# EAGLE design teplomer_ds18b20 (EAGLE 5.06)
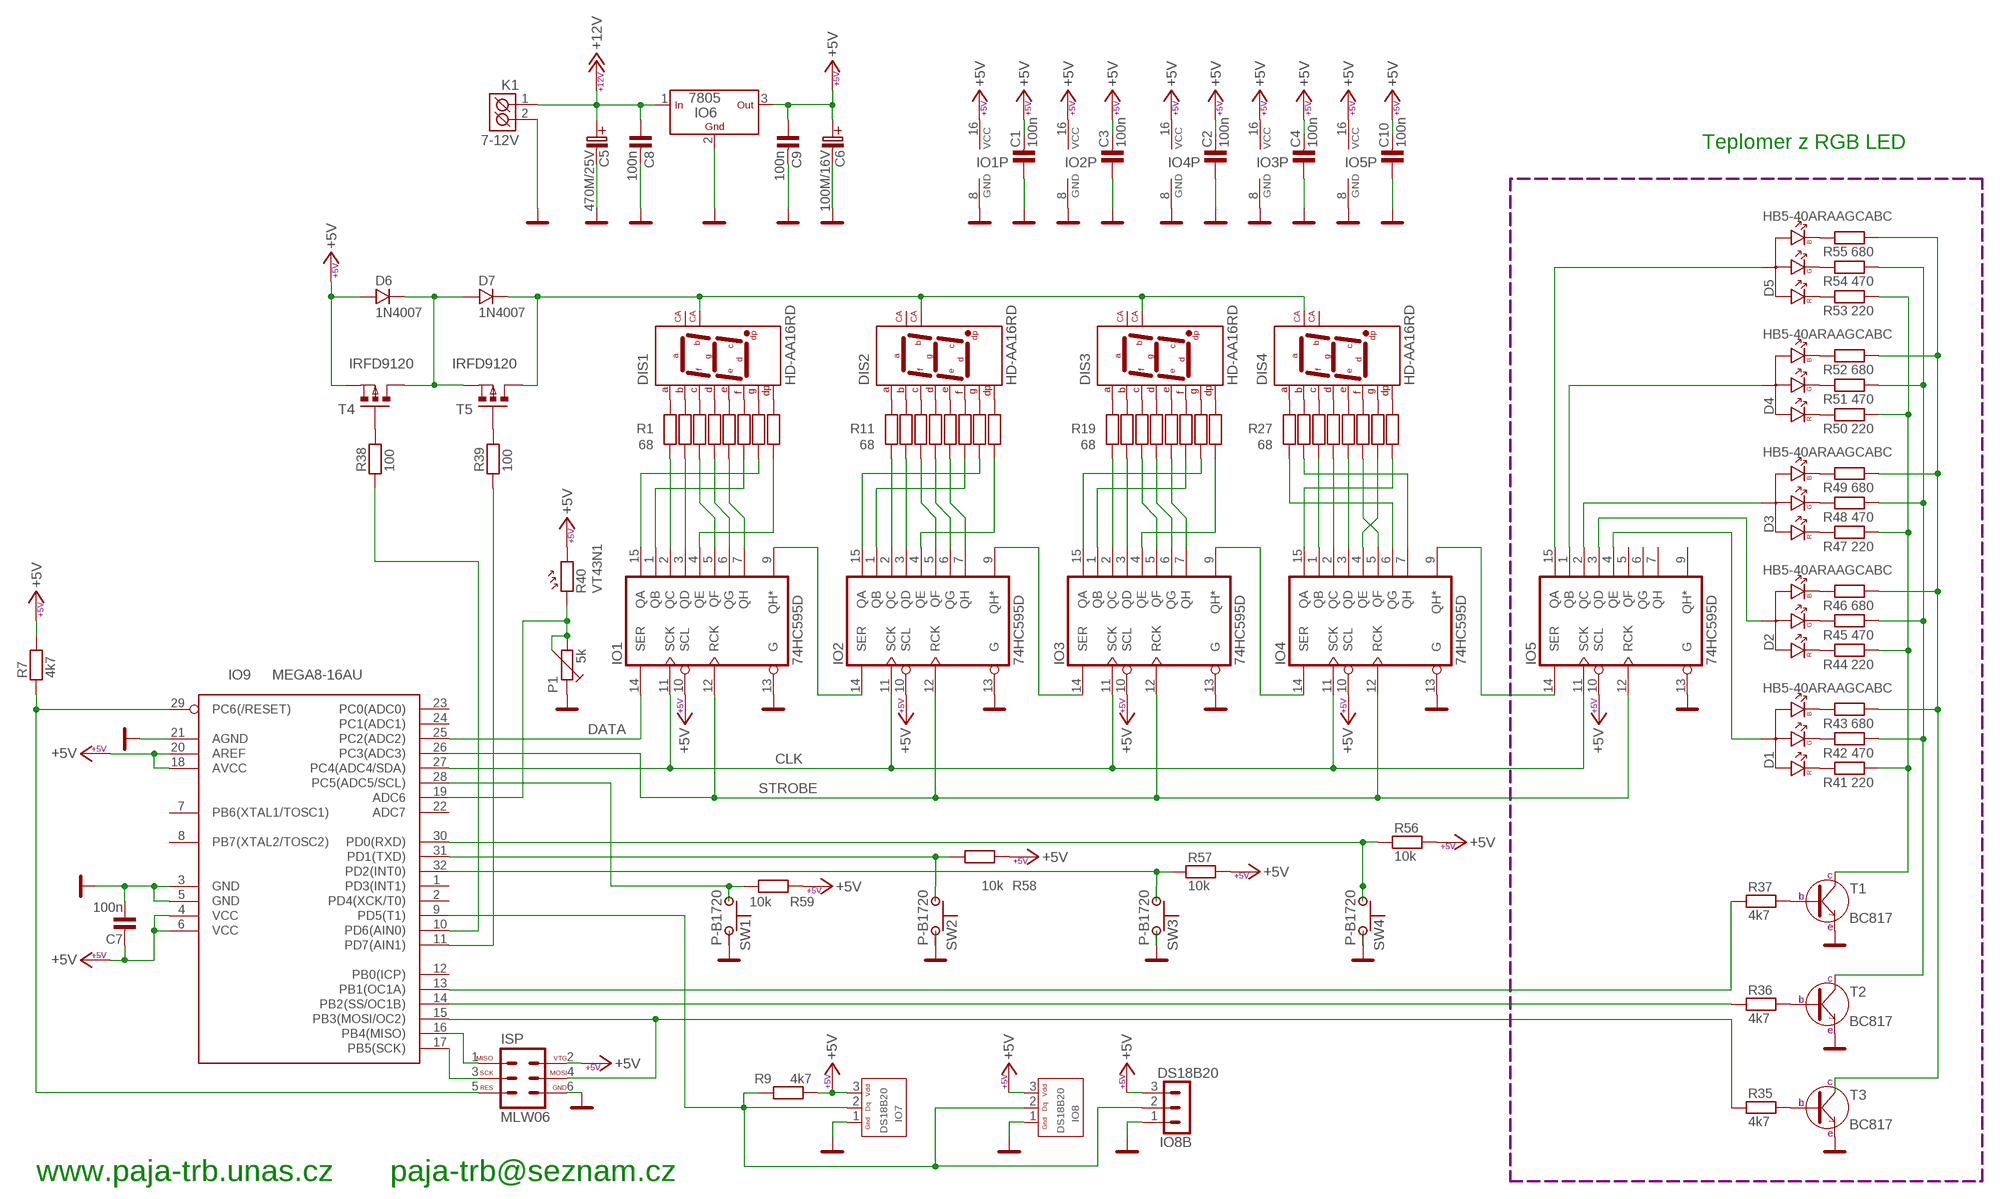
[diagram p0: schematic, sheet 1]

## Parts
C1  100n  C-KERAMIK_SMD_1206  [1206]
C2  100n  C-KERAMIK_SMD_1206  [1206]
C3  100n  C-KERAMIK_SMD_1206  [1206]
C4  100n  C-KERAMIK_SMD_1206  [1206]
C5  470M/25V  [C_EL_5]
C6  100M/16V  [C_EL_2,5]
C7  100n  C-KERAMIK_SMD_1206  [1206]
C8  100n  C-KERAMIK_SMD_1206  [1206]
C9  100n  C-KERAMIK_SMD_1206  [1206]
C10  100n  C-KERAMIK_SMD_1206  [1206]
D1  HB5-40ARAAGCABC  LED_RGB  [LED_5-RGB]
D2  HB5-40ARAAGCABC  LED_RGB  [LED_5-RGB]
D3  HB5-40ARAAGCABC  LED_RGB  [LED_5-RGB]
D4  HB5-40ARAAGCABC  LED_RGB  [LED_5-RGB]
D5  HB5-40ARAAGCABC  LED_RGB  [LED_5-RGB]
D6  1N4007  1N4007_SM-1  [SM-1]
D7  1N4007  1N4007_SM-1  [SM-1]
DIS1  HD-AA16RD  HD-AA11RD  [HD-AA]
DIS2  HD-AA16RD  HD-AA11RD  [HD-AA]
DIS3  HD-AA16RD  HD-AA11RD  [HD-AA]
DIS4  HD-AA16RD  HD-AA11RD  [HD-AA]
IO1  74HC595D  [SO16]
IO2  74HC595D  [SO16]
IO3  74HC595D  [SO16]
IO4  74HC595D  [SO16]
IO5  74HC595D  [SO16]
IO6  7805  78_LEZ_LEZ  [TO-220]
IO7  DS18B20  DS18B20TO-92  [TO-92]
IO8  DS18B20  DS18B20TO-92  [TO-92]
IO8B  DS18B20  PSH02-03W  [PSH02-03W]
IO9  MEGA8-16AU  MEGA8-AI  [TQFP32-08]
ISP  MLW06  AVR_ISP  [MLW06G]
K1  7-12V  ARK500/2  [ARK500/2]
P1  5k  TRIMRPT6V  [PT6V]
R1  68  R_SMD_1206  [1206]
R2  68  R_SMD_1206  [1206]
R3  68  R_SMD_1206  [1206]
R4  68  R_SMD_1206  [1206]
R5  68  R_SMD_1206  [1206]
R6  68  R_SMD_1206  [1206]
R7  4k7  R_SMD_1206  [1206]
R8  68  R_SMD_1206  [1206]
R9  4k7  R_SMD_1206  [1206]
R10  470  R_SMD_1206  [1206]
R11  68  R_SMD_1206  [1206]
R12  68  R_SMD_1206  [1206]
R13  68  R_SMD_1206  [1206]
R14  68  R_SMD_1206  [1206]
R15  68  R_SMD_1206  [1206]
R16  68  R_SMD_1206  [1206]
R17  68  R_SMD_1206  [1206]
R18  470  R_SMD_1206  [1206]
R19  68  R_SMD_1206  [1206]
R20  68  R_SMD_1206  [1206]
R21  68  R_SMD_1206  [1206]
R22  68  R_SMD_1206  [1206]
R23  68  R_SMD_1206  [1206]
R24  68  R_SMD_1206  [1206]
R25  68  R_SMD_1206  [1206]
R26  470  R_SMD_1206  [1206]
R27  68  R_SMD_1206  [1206]
R28  68  R_SMD_1206  [1206]
R29  68  R_SMD_1206  [1206]
R30  68  R_SMD_1206  [1206]
R31  68  R_SMD_1206  [1206]
R32  68  R_SMD_1206  [1206]
R33  470  R_SMD_1206  [1206]
R34  68  R_SMD_1206  [1206]
R35  4k7  R_SMD_1206  [1206]
R36  4k7  R_SMD_1206  [1206]
R37  4k7  R_SMD_1206  [1206]
R38  100  R_7,5  [R-7,5]
R39  100  R_7,5  [R-7,5]
R40  VT43N1  R-FOTO  [R-FOTO]
R41  220  R_SMD_0805  [0805]
R42  470  R_SMD_1206  [1206]
R43  680  R_SMD_1206  [1206]
R44  220  R_SMD_0805  [0805]
R45  470  R_SMD_1206  [1206]
R46  680  R_SMD_1206  [1206]
R47  220  R_SMD_0805  [0805]
R48  470  R_SMD_1206  [1206]
R49  680  R_SMD_1206  [1206]
R50  220  R_SMD_0805  [0805]
R51  470  R_SMD_1206  [1206]
R52  680  R_SMD_1206  [1206]
R53  220  R_SMD_0805  [0805]
R54  470  R_SMD_1206  [1206]
R55  680  R_SMD_1206  [1206]
R56  10k  R_10  [R-10]
R57  10k  R_7,5  [R-7,5]
R58  10k  R_SMD_1206  [1206]
R59  10k  R_10  [R-10]
SW1  P-B1720  [P-B1720]
SW2  P-B1720  [P-B1720]
SW3  P-B1720  [P-B1720]
SW4  P-B1720  [P-B1720]
T1  BC817  [SOT-23]
T2  BC817  [SOT-23]
T3  BC817  [SOT-23]
T4  IRFD9120  IRFD9120*  [DIL04]
T5  IRFD9120  IRFD9120*  [DIL04]

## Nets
0,7: IO9.10(PD6(AIN0)) R38.1
1,4: IO9.11(PD7(AIN1)) R39.1
1WIRE: IO7.2(1WIRE) IO8.2(1WIRE) IO8B.2 IO9.9(PD5(T1)) R9.1
+5V: C1.2 C2.2 C3.2 C4.2 C6.C+(C_EL+) C7.2 C9.1 C10.2 D6.A IO1.10(SCL) IO1.16(VCC) IO2.10(SCL) IO2.16(VCC) IO3.10(SCL) IO3.16(VCC) IO4.10(SCL) IO4.16(VCC) IO5.10(SCL) IO5.16(VCC) IO6.3(OUT) IO7.3(+VCC) IO8.3(+VCC) IO8B.3 IO9.4(VCC) IO9.6(VCC) IO9.18(AVCC) IO9.20(AREF) ISP.2 R7.2 R9.2 R40.2 R56.2 R57.2 R58.2 R59.2 T4.2(S)
+12V: C5.C+(C_EL+) C8.1 IO6.1(IN) K1.1(K1)
B: IO9.14(PB2(SS/OC1B)) R36.1
CLK: IO1.11(SCK) IO2.11(SCK) IO3.11(SCK) IO4.11(SCK) IO5.11(SCK) IO9.27(PC4(ADC4/SDA))
DATA: IO1.14(SER) IO9.25(PC2(ADC2))
G: IO9.15(PB3(MOSI/OC2)) ISP.4 R35.1
GND: C1.1 C2.1 C3.1 C4.1 C5.C-(C_EL-) C6.C-(C_EL-) C7.1 C8.2 C9.2 C10.1 IO1.8(GND) IO1.13(G) IO2.8(GND) IO2.13(G) IO3.8(GND) IO3.13(G) IO4.8(GND) IO4.13(G) IO5.8(GND) IO5.13(G) IO6.2(GND) IO7.1(GND) IO8.1(GND) IO8B.1 IO9.3(GND) IO9.5(GND) IO9.21(AGND) ISP.6 K1.2(K2) P1.1 SW1.2 SW1.4 SW2.2 SW2.4 SW3.2 SW3.4 SW4.2 SW4.4 T1.2(E) T2.2(E) T3.2(E)
MISO: IO9.16(PB4(MISO)) ISP.1
N$1: D6.K D7.A T4.3(D) T5.2(S)
N$2: IO9.19(ADC6) P1.2 P1.3 R40.1
N$3: IO1.9(QH*) IO2.14(SER)
N$4: IO2.9(QH*) IO3.14(SER)
N$5: DIS1.5(DP) R10.2
N$6: IO1.1(QB) R6.1
N$7: IO1.15(QA) R8.1
N$8: IO4.9(QH*) IO5.14(SER)
N$9: IO1.2(QC) R1.1
N$10: IO1.3(QD) R2.1
N$11: IO1.4(QE) R10.1
N$12: IO1.5(QF) R3.1
N$13: D1.2(A) IO5.4(QE)
N$14: DIS1.7(A) R1.2
N$15: DIS1.6(B) R2.2
N$16: DIS1.4(C) R3.2
N$17: DIS1.2(D) R4.2
N$18: DIS1.1(E) R5.2
N$19: DIS1.9(F) R6.2
N$20: DIS1.10(G) R8.2
N$21: IO1.6(QG) R4.1
N$22: IO1.7(QH) R5.1
N$23: IO2.1(QB) R16.1
N$24: IO2.15(QA) R17.1
N$25: IO2.2(QC) R11.1
N$26: IO2.3(QD) R12.1
N$27: IO2.4(QE) R18.1
N$28: IO2.5(QF) R13.1
N$29: IO2.6(QG) R14.1
N$30: IO2.7(QH) R15.1
N$31: DIS2.7(A) R11.2
N$32: DIS2.6(B) R12.2
N$33: DIS2.4(C) R13.2
N$34: DIS2.2(D) R14.2
N$35: DIS2.1(E) R15.2
N$36: DIS2.9(F) R16.2
N$37: DIS2.10(G) R17.2
N$38: DIS2.5(DP) R18.2
N$39: IO3.1(QB) R24.1
N$40: IO3.15(QA) R25.1
N$41: IO3.2(QC) R19.1
N$42: IO3.3(QD) R20.1
N$43: IO3.4(QE) R26.1
N$44: IO3.9(QH*) IO4.14(SER)
N$45: IO3.5(QF) R21.1
N$46: IO3.6(QG) R22.1
N$47: IO3.7(QH) R23.1
N$48: IO4.1(QB) R32.1
N$49: IO4.15(QA) R33.1
N$50: IO4.2(QC) R27.1
N$51: IO4.3(QD) R28.1
N$52: IO4.4(QE) R34.1
N$53: IO4.5(QF) R29.1
N$54: IO4.6(QG) R30.1
N$55: IO4.7(QH) R31.1
N$56: DIS3.7(A) R19.2
N$57: DIS3.6(B) R20.2
N$58: DIS3.4(C) R21.2
N$59: DIS3.2(D) R22.2
N$60: DIS3.1(E) R23.2
N$61: DIS3.9(F) R24.2
N$62: DIS3.10(G) R25.2
N$63: DIS3.5(DP) R26.2
N$64: DIS4.2(D) R27.2
N$65: DIS4.1(E) R28.2
N$66: DIS4.9(F) R29.2
N$67: DIS4.7(A) R30.2
N$68: DIS4.6(B) R31.2
N$69: DIS4.4(C) R32.2
N$70: DIS4.5(DP) R33.2
N$71: DIS4.10(G) R34.2
N$72: IO9.31(PD1(TXD)) R58.1 SW2.1 SW2.3
N$73: R37.2 T1.1(B)
N$74: R36.2 T2.1(B)
N$75: R35.2 T3.1(B)
N$76: R43.1 R46.1 R49.1 R52.1 R55.1 T3.3(C)
N$77: R42.1 R45.1 R48.1 R51.1 R54.1 T2.3(C)
N$78: R41.1 R44.1 R47.1 R50.1 R53.1 T1.3(C)
N$79: D2.2(A) IO5.3(QD)
N$80: D3.2(A) IO5.2(QC)
N$81: D4.2(A) IO5.1(QB)
N$82: D5.2(A) IO5.15(QA)
N$83: IO9.30(PD0(RXD)) R56.1 SW4.1 SW4.3
N$84: IO9.28(PC5(ADC5/SCL)) R59.1 SW1.1 SW1.3
N$85: D1.1(R) R41.2
N$86: R38.2 T4.1(G)
N$87: R39.2 T5.1(G)
N$88: IO9.32(PD2(INT0)) R57.1 SW3.1 SW3.3
N$89: D1.3(G) R42.2
N$90: D1.4(B) R43.2
N$91: D2.1(R) R44.2
N$92: D2.3(G) R45.2
N$93: D2.4(B) R46.2
N$94: D3.1(R) R47.2
N$95: D3.3(G) R48.2
N$96: D3.4(B) R49.2
N$97: D4.1(R) R50.2
N$98: D4.3(G) R51.2
N$99: D4.4(B) R52.2
N$100: D5.1(R) R53.2
N$101: D5.3(G) R54.2
N$102: D5.4(B) R55.2
N$103: D7.K DIS1.8(CA2) DIS2.8(CA2) DIS3.8(CA2) DIS4.3(CA1) T5.3(D)
R: IO9.13(PB1(OC1A)) R37.1
RESET: IO9.29(PC6(/RESET)) ISP.5 R7.1
SCK: IO9.17(PB5(SCK)) ISP.3
STROBE: IO1.12(RCK) IO2.12(RCK) IO3.12(RCK) IO4.12(RCK) IO5.12(RCK) IO9.26(PC3(ADC3))
Unconnected: DIS1.3(CA1) DIS2.3(CA1) DIS3.3(CA1) DIS4.8(CA2) IO5.5(QF) IO5.6(QG) IO5.7(QH) IO5.9(QH*) IO9.1(PD3(INT1)) IO9.2(PD4(XCK/T0)) IO9.7(PB6(XTAL1/TOSC1)) IO9.8(PB7(XTAL2/TOSC2)) IO9.12(PB0(ICP)) IO9.22(ADC7) IO9.23(PC0(ADC0)) IO9.24(PC1(ADC1))

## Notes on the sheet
- Teplomer z RGB LED
- www.paja-trb.unas.cz | paja-trb@seznam.cz

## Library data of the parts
C1-C4 C7-C10 = #PaJa_23_e56:C-KERAMIK: Kondenzator - keramicky
C5 = #PaJa_C-el_2:470M/25V
C6 = #PaJa_C-el_2:100M/16V
D1-D5 = #PaJa_23_e56:LED_RGB: LED dioda - RGB - trojbarevna - 4 vyvody, spol. Anoda
D6 D7 = #PaJa_23_e56:1N4007: Usmernovaci dioda - 1A, 1000V
DIS1-DIS4 = #_GM99:HD-AA11RD
IO1-IO5 = 74xx-eu:74*595: 8-bit SHIFT REGISTER, output latch
IO6 = #PaJa_23_e56:78??: Stabilizátor - 1A a 1,5A ?? - napeti => 05, 06, 08, 09, 12, 15, 18, 20, 24 => 1,5A ?? - napeti => 10, 12, 15, 18 => 1A S ?? - napeti => 05, 09, 10, 12, 15, 18, 24 => 2A T ?? - napeti => 05 => 3A
IO7 IO8 = #PaJa_23_e56:DS18B20: DS18B20 - teplomer, 1wire (-55 az 125°C)
IO8B = #PaJa_23_e56:PSH02-03: Konektory se zamkem - vidlice - 3pin
IO9 = atmel-1:MEGA8: MICROCONTROLLER 8 Kbytes FLASH 1 kbytes SRAM 512 bytes EEPROM USART 6-channel 10 bit ADC 2-channel 8 bit ADC
ISP = #PaJa_23_e56:AVR_ISP
K1 = #PaJa_23_e56:ARK500/2: Svorkovnice - roztec 5mm - dvojita
P1 = #PaJa_23_e56:TRIMR: Trimr
R1-R39 R41-R55 = #PaJa_23_e56:R: Rezistor
R40 = #PaJa_23_e56:R-FOTO: Foto odpor
R56-R59 = #PaJa_23:R: Rezistor
SW1-SW4 = #PaJa_23_e56:P-B1720: &micro;-tlacitko
T1-T3 = #PaJa_23_e56:BC817: SMD tranzistor - NPN - ekv. BC337
T4 T5 = #hacesoft:IRFD9120

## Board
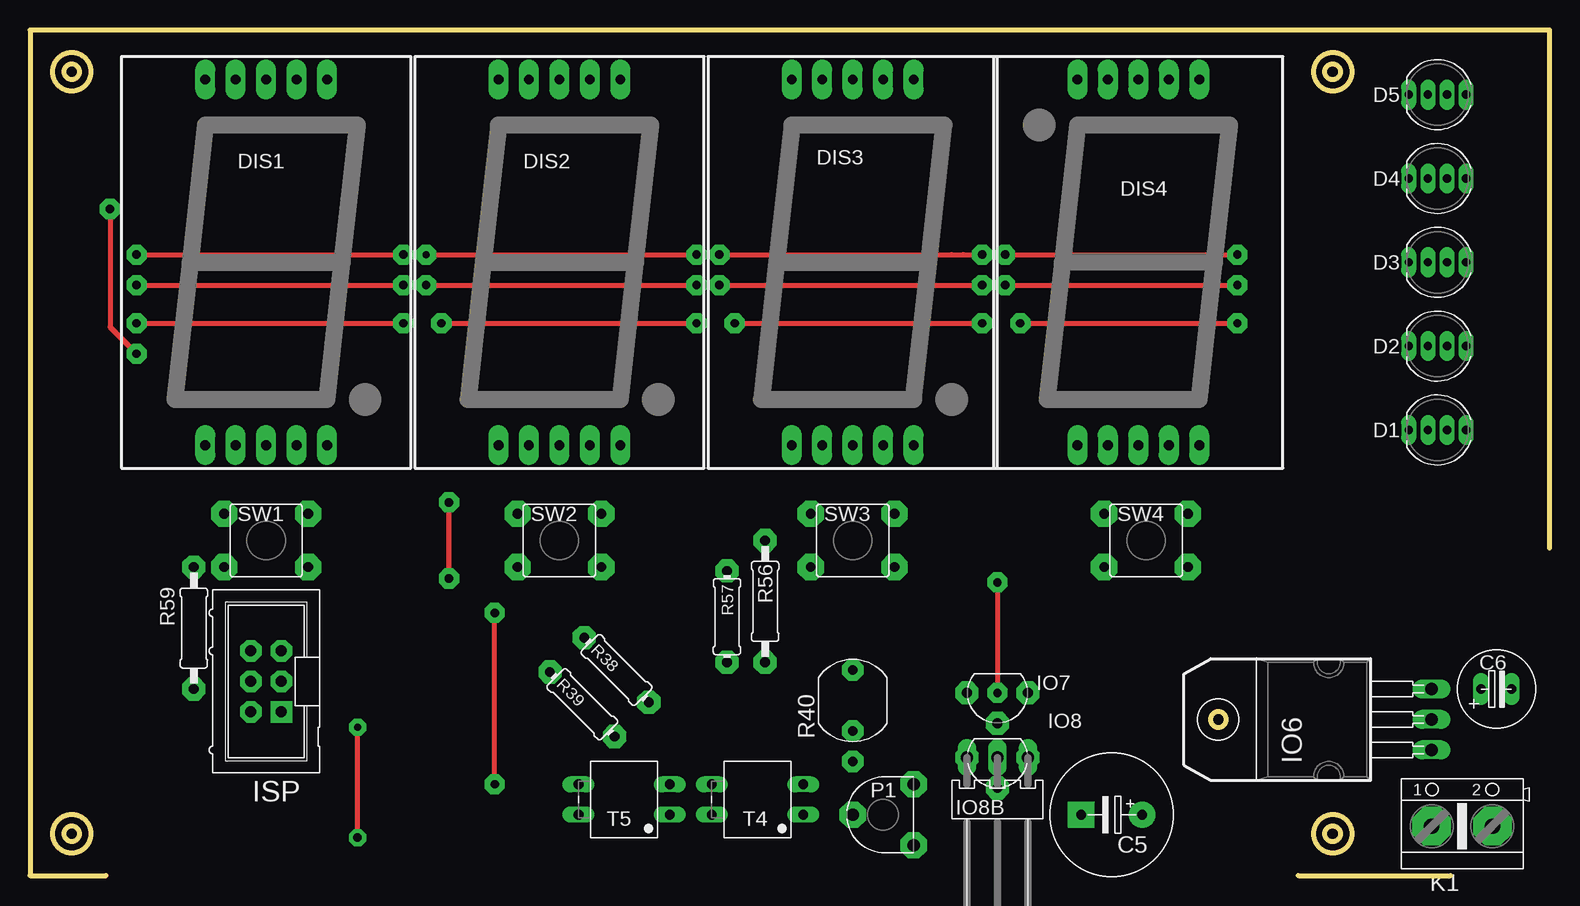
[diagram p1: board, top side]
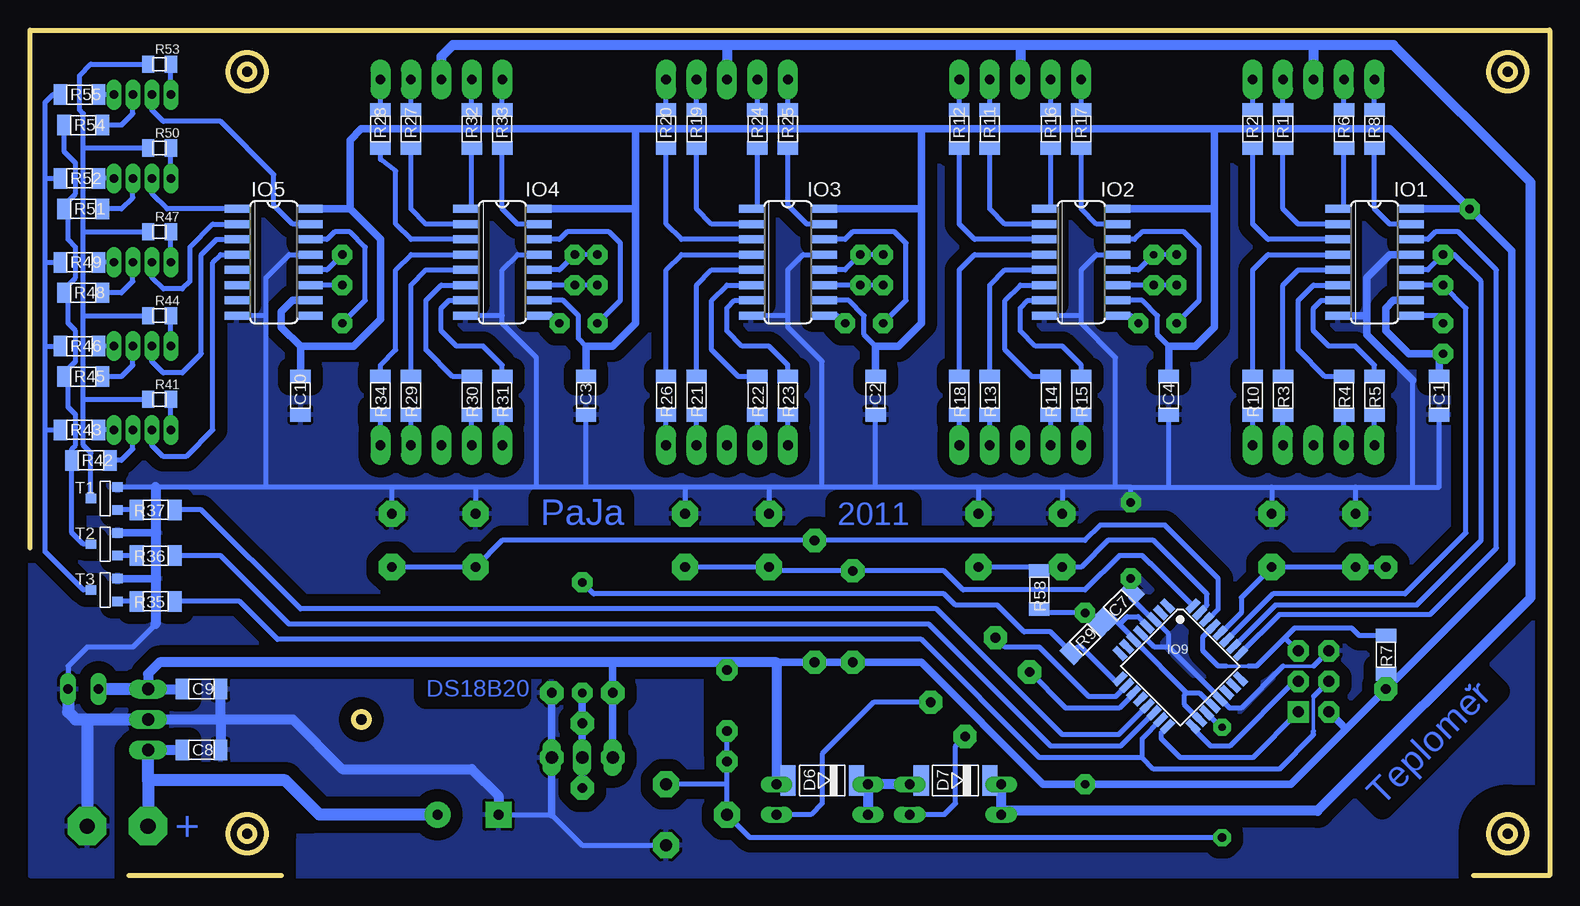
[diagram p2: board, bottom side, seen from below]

Size 126.68 x 70.47 mm. Coordinates in mm from the lower left corner, seen from the top.
Outline: 126.68,27.3 126.67,70.47 0,70.47 0,0 6.35,0
Outline: 105.73,0 118.43,0
Outline: circle at 99.06,13.02 radius 0.64
Outline: circle at 108.58,3.49 radius 1.59
Outline: circle at 3.49,3.49 radius 1.59
Outline: circle at 3.49,3.49 radius 0.64
Outline: circle at 3.49,66.99 radius 0.64
Outline: circle at 3.49,66.99 radius 1.59
Outline: circle at 108.58,66.99 radius 0.64
Outline: circle at 108.58,66.99 radius 1.59
Outline: circle at 108.58,3.49 radius 0.64
Copper layers (1*16): Top 0.035mm / dielectric 1.5mm / Bottom 0.035mm
Design rules "default": minimum track width 10mil, minimum drill 24mil, track to track 8mil, track to pad 8mil, pad to pad 8mil, via to via 8mil, smd to smd 8mil, copper to edge 40mil, drill to drill 8mil, minimum pad ring 10mil, minimum via ring 8mil, stop-mask expansion 4mil, vias tented up to drill 0mil, thermal gap 10mil
Holes 3.2 mm at 3.49,3.49 3.49,66.99 108.58,66.99 108.58,3.49
bRestrict: area 35.9,22.2 to 37.1,24.1; area 0.6,0.6 to 6.3,6.3; area 105.7,0.6 to 111.4,6.3; 6 lines

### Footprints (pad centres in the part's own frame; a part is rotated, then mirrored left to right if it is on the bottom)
1206 = smd 1.143 x 1.702: 1 -1.587,0; 2 1.587,0
C_EL_5 = drill 0.813 pad 2.184 round: C+ -2.54,0 | drill 0.813 pad 2.184 square: C- 2.54,0
C_EL_2,5 = drill 0.813 pad 1.27 long: C+ -1.27,0; C- 1.27,0
LED_5-RGB = drill 0.7 pad 1.27 long: 1 -2.54,0; 2 -0.953,0; 3 0.635,0; 4 2.223,0
SM-1 = smd 1.27 x 2.54: A 2.857,0; K -2.857,0
HD-AA = drill 0.813 pad 1.676 long: 1 0,0; 2 2.54,0; 3 5.08,0; 4 7.62,0; 5 10.16,0; 6 10.16,30.48; 7 7.62,30.48; 8 5.08,30.48; 9 2.54,30.48; 10 0,30.48
SO16 = smd 0.66 x 2.032: 1 -4.445,-3.073; 2 -3.175,-3.073; 3 -1.905,-3.073; 4 -0.635,-3.073; 5 0.635,-3.073; 6 1.905,-3.073; 7 3.175,-3.073; 8 4.445,-3.073; 9 4.445,3.073; 10 3.175,3.073; 11 1.905,3.073; 12 0.635,3.073; 13 -0.635,3.073; 14 -1.905,3.073; 15 -3.175,3.073; 16 -4.445,3.073
TO-220 = drill 1.016 pad 1.6 long: 1 -2.54,0; 2 0,0; 3 2.54,0
TO-92 = drill 0.813 pad 1.93 octagon: 1 0,2.54; 2 2.54,0; 3 0,-2.54
PSH02-03W = drill 1.016 pad 1.422 long: 1 -2.54,0; 2 0,0; 3 2.54,0
TQFP32-08 = smd 1.27 x 0.559: 1 -4.293,2.8; 2 -4.293,2; 3 -4.293,1.2; 4 -4.293,0.4; 5 -4.293,-0.4; 6 -4.293,-1.2; 7 -4.293,-2; 8 -4.293,-2.8; 17 4.293,-2.8; 18 4.293,-2; 19 4.293,-1.2; 20 4.293,-0.4; 21 4.293,0.4; 22 4.293,1.2; 23 4.293,2; 24 4.293,2.8 | smd 0.559 x 1.27: 9 -2.8,-4.293; 10 -2,-4.293; 11 -1.2,-4.293; 12 -0.4,-4.293; 13 0.4,-4.293; 14 1.2,-4.293; 15 2,-4.293; 16 2.8,-4.293; 25 2.8,4.293; 26 2,4.293; 27 1.2,4.293; 28 0.4,4.293; 29 -0.4,4.293; 30 -1.2,4.293; 31 -2,4.293; 32 -2.8,4.293
MLW06G = drill 0.914 pad 1.778 square: 1 -2.54,-1.27 | drill 0.914 pad 1.778 octagon: 2 -2.54,1.27; 3 0,-1.27; 4 0,1.27; 5 2.54,-1.27; 6 2.54,1.27
ARK500/2 = drill 1.27 pad 3.2 octagon: 1 -2.54,0; 2 2.54,0
PT6V = drill 1.016 pad 2.184 octagon: 1 -2.54,-2.54; 2 0,2.54; 3 2.54,-2.54
R-7,5 = drill 0.813 pad 1.93 octagon: 1 -3.81,0; 2 3.81,0
R-FOTO = drill 0.813 pad 1.778 octagon: 1 -2.54,0; 2 2.54,0
0805 = smd 1.016 x 1.422: 1 -0.953,0; 2 0.953,0
R-10 = drill 0.813 pad 1.93 octagon: 1 -5.08,0; 2 5.08,0
P-B1720 = drill 0.813 pad 2.184 octagon: 1 -3.493,-2.223; 2 -3.493,2.223; 3 3.493,-2.223; 4 3.493,2.223
SOT-23 = smd 0.787 x 0.889: 1 -0.953,-0.953; 2 0.953,-0.953; 3 0,1.27
DIL04 = drill 0.813 long: 1 -1.27,-3.81; 2 1.27,-3.81; 3 1.27,3.81; 4 -1.27,3.81

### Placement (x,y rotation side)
C1  9.21,40.01 90 bottom
C2  56.2,40.01 90 bottom
C3  80.33,40.01 90 bottom
C4  31.75,40.01 90 bottom
C5  90.17,5.08 180 top
C6  122.24,15.56 0 top
C7  35.88,22.54 225 bottom
C8  112.39,10.48 0 bottom
C9  112.39,15.56 0 bottom
C10  104.14,40.01 90 bottom
D1  117.47,37.15 0 top
D2  117.47,44.13 0 top
D3  117.47,51.12 0 top
D4  117.47,58.1 0 top
D5  117.47,65.09 0 top
D6  60.64,7.94 180 bottom
D7  49.53,7.94 180 bottom
DIS1  14.61,35.88 0 top
DIS2  39.05,35.88 0 top
DIS3  63.5,35.88 0 top
DIS4  97.47,66.36 180 top
IO1  14.61,51.12 270 bottom
IO2  39.05,51.12 270 bottom
IO3  63.5,51.12 270 bottom
IO4  87.31,51.12 270 bottom
IO5  106.36,51.12 270 bottom
IO6  116.84,13.02 90 top
IO7  80.64,15.24 270 top
IO8  80.64,9.84 270 top
IO8B  80.64,9.84 180 top
IO9  30.8,17.46 315 bottom
ISP  19.68,16.19 90 top
K1  119.38,4.13 0 top
P1  71.12,5.08 90 top
R1  22.23,62.23 90 bottom
R2  24.77,62.23 90 bottom
R3  22.23,40.01 270 bottom
R4  17.14,40.01 270 bottom
R5  14.61,40.01 270 bottom
R6  17.14,62.23 90 bottom
R7  13.65,18.41 270 bottom
R8  14.61,62.23 90 bottom
R9  38.73,19.68 45 bottom
R10  24.77,40.01 270 bottom
R11  46.67,62.23 90 bottom
R12  49.21,62.23 90 bottom
R13  46.67,40.01 270 bottom
R14  41.59,40.01 270 bottom
R15  39.05,40.01 270 bottom
R16  41.59,62.23 90 bottom
R17  39.05,62.23 90 bottom
R18  49.21,40.01 270 bottom
R19  71.12,62.23 90 bottom
R20  73.66,62.23 90 bottom
R21  71.12,40.01 270 bottom
R22  66.04,40.01 270 bottom
R23  63.5,40.01 270 bottom
R24  66.04,62.23 90 bottom
R25  63.5,62.23 90 bottom
R26  73.66,40.01 270 bottom
R27  94.93,62.23 90 bottom
R28  97.47,62.23 90 bottom
R29  94.93,40.01 270 bottom
R30  89.85,40.01 270 bottom
R31  87.31,40.01 270 bottom
R32  89.85,62.23 90 bottom
R33  87.31,62.23 90 bottom
R34  97.47,40.01 270 bottom
R35  116.2,22.86 180 bottom
R36  116.2,26.67 180 bottom
R37  116.2,30.48 180 bottom
R38  48.9,17.14 315 top
R39  46.04,14.29 315 top
R40  68.58,14.61 90 top
R41  115.89,39.69 0 bottom
R42  121.6,34.61 0 bottom
R43  122.56,37.15 0 bottom
R44  115.89,46.67 0 bottom
R45  122.24,41.59 0 bottom
R46  122.56,44.13 0 bottom
R47  115.89,53.66 0 bottom
R48  122.24,48.58 0 bottom
R49  122.56,51.12 0 bottom
R50  115.89,60.64 0 bottom
R51  122.24,55.56 0 bottom
R52  122.56,58.1 0 bottom
R53  115.89,67.63 0 bottom
R54  122.24,62.55 0 bottom
R55  122.56,65.09 0 bottom
R56  61.28,22.86 270 top
R57  58.1,21.59 270 top
R58  42.55,23.81 270 bottom
R59  13.65,20.64 270 top
SW1  19.68,27.94 0 top
SW2  44.13,27.94 0 top
SW3  68.58,27.94 0 top
SW4  93.03,27.94 0 top
T1  120.33,31.43 90 bottom
T2  120.33,27.62 90 bottom
T3  120.33,23.81 90 bottom
T4  60.64,6.35 90 top
T5  49.53,6.35 90 top

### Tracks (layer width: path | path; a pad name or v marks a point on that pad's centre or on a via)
0,7
  Bottom 0.406: IO9.10 35.28,15.84 36.2,14.92 38.42,14.92 42.55,19.05 45.4,19.05 45.87,19.52 R38.1
1,4
  Bottom 0.406: IO9.11 34.68,15.17 35.88,13.97 40.33,13.97 R39.1
1WIRE  (via drill 0.7 pad 1.68)
  Top 0.406: v80.64,24.45 v80.64,15.24
  Bottom 0.406: IO9.9 36.03,16.19 36.2,16.19 39.05,19.05 39.37,19.05 R9.1 41.62,20.32 43.81,20.32 46.04,22.54 49.53,22.54 50.48,23.5 79.69,23.5 v80.64,24.45
  Bottom 0.61: v80.64,15.24 IO7.2 IO8B.2 IO8.2
+5V  (via drill 0.7 pad 1.68)
  Top 0.406: v6.67,55.56 6.67,45.72 v8.89,43.5 | v38.73,7.62 v38.73,21.91
  Bottom 0.406: IO9.4 33.55,20.85 34.29,21.59 35.24,21.59 35.88,20.95 | 35.88,20.95 34.68,19.76 IO9.6 30.27,15.24 | 35.88,20.95 36.51,21.59 37.17,21.59 | IO2.10 33.97,47.94 32.7,46.67 32.7,45.09 31.75,44.13 | IO3.10 58.42,47.94 57.15,46.67 57.15,45.09 56.2,44.13 | IO4.10 82.23,47.94 80.96,46.67 80.96,44.77 80.33,44.13 | 37.17,21.59 C7.2 R9.2 | 38.73,21.59 37.17,21.59 | 38.73,21.59 39.05,21.59 | 38.73,21.59 v38.73,21.91 42.55,21.91 R58.2 | IO9.20 28.11,14.14 29.21,15.24 30.27,15.24 | IO9.18 29.2,13.01 30.48,14.29 30.48,15.03 30.27,15.24 | 68.58,17.78 R40.2 | v8.89,43.5 9.21,43.5 | 17.46,12.7
  Bottom 0.61: 27.94,62.23 13.34,62.23 v6.67,55.56 | 27.94,62.23 52.39,62.23 | 52.39,62.23 76.2,62.23 | 27.94,62.23 27.94,55.56 | 76.2,62.23 99.06,62.23 100.01,61.28 100.01,55.56 | IO1.10 13.02,47.94 13.65,47.31 13.65,45.4 11.75,43.5 9.21,43.5 C1.2 | v6.67,55.56 IO1.16 | 27.94,55.56 IO2.16 | 27.94,55.56 27.94,45.72 29.53,44.13 31.75,44.13 C4.2 | 52.39,55.56 52.39,46.04 54.29,44.13 56.2,44.13 C2.2 | 52.39,55.56 IO3.16 | 52.39,62.23 52.39,55.56 | 76.2,62.23 76.2,55.56 | 76.2,55.56 76.2,46.04 78.11,44.13 80.33,44.13 C3.2 | 76.2,55.56 IO4.16 | IO5.10 104.78,47.94 105.73,46.99 105.73,45.72 104.14,44.13 | 104.14,44.13 99.69,44.13 97.47,46.35 97.47,53.02 100.01,55.56 | 100.01,55.56 IO5.16 | v6.67,55.56 3.17,52.07 3.17,26.04 R59.2 | ISP.2 17.46,12.7 16.99,12.22 | IO8B.3 IO7.3 78.11,17.78 | 64.45,17.78 R56.2 R57.2 52.39,17.78 42.23,7.62 v38.73,7.62 21.59,7.62 16.99,12.22 | 104.14,44.13 C10.2 | 16.99,12.22 R59.2 | R59.2 R7.2
  Bottom 0.813: C9.1 IO6.3 116.84,16.83 115.89,17.78 78.11,17.78 68.58,17.78 64.45,17.78 T4.2 D6.A
  Bottom 1.016: IO6.3 C6.C+
+12V
  Bottom 0.813: IO6.1 C8.1
  Bottom 1.016: 116.84,7.94 K1.1 | C5.C+ 102.55,5.08 105.41,7.94 116.84,7.94 | 116.84,7.94 IO6.1
B
  Bottom 0.406: IO9.14 35.77,10.79 41.59,10.79 51.75,20.95 105.09,20.95 110.81,26.67 R36.1
CLK  (via drill 0.7 pad 1.68)
  Top 0.406: v8.89,49.21 v31.11,49.21 v33.02,49.21 v55.56,49.21 v57.47,49.21 v79.38,49.21 v81.28,49.21 v100.65,49.21
  Bottom 0.406: IO1.11 v8.89,49.21 6.99,47.31 6.99,28.57 12.06,23.5 23.07,23.5 IO9.27 | v31.11,49.21 v33.02,49.21 IO2.11 | v55.56,49.21 v57.47,49.21 IO3.11 | v81.28,49.21 v79.38,49.21 v81.28,49.21 | v81.28,49.21 IO4.11 | v100.65,49.21 IO5.11
DATA
  Bottom 0.406: IO1.14 10.16,53.02 9.53,53.66 7.62,53.66 4.45,50.48 4.45,27.3 10,21.75 22.55,21.75 IO9.25
G
  Bottom 0.305: 19.68,12.06 19.68,14.92
  Bottom 0.406: IO9.15 32.42,12.98 33.97,11.43 33.97,9.84 | 19.68,12.06 19.68,11.75 22.54,8.89 33.02,8.89 33.97,9.84 | 19.68,14.92 ISP.4 | 33.97,9.84 42.55,9.84 52.39,19.68 106.05,19.68 109.22,22.86 R35.1
GND  (via drill 0.7 pad 1.68)
  Top 0.406: v34.92,24.77 v34.92,31.11
  Bottom 0.305: 19.68,17.46 22.23,17.46
  Bottom 0.406: 31.75,19.05 31.75,20.11 IO9.3 33.09,21.35 34.92,23.18 | 31.75,19.05 32.95,19.05 IO9.5 | 27.48,14.78 IO9.21 | 27.48,14.78 31.75,19.05 | 34.92,23.18 34.92,23.84 C7.1 | 23.18,32.38 16.19,32.38 | 31.75,32.38 23.18,32.38 | 40.64,32.38 47.62,32.38 | 65.09,32.38 72.07,32.38 | IO2.13 37.78,51.75 39.05,50.48 39.05,46.67 | IO3.13 62.23,51.75 63.5,50.48 63.5,46.67 | 63.5,46.67 IO3.8 | IO4.13 86.04,51.75 87.31,50.48 87.31,46.67 | 39.05,46.67 IO2.8 | 39.05,46.67 39.05,46.04 36.2,43.18 36.2,32.38 | 63.5,46.67 63.5,45.72 60.64,42.86 60.64,32.38 | 87.31,46.67 IO4.8 | 31.75,32.38 C4.1 | 11.43,32.38 11.43,41.27 | 16.19,32.38 11.43,32.38 | 87.31,46.67 87.31,46.04 84.45,43.18 84.45,32.38 | IO5.13 105.09,51.75 107,49.85 107,46.67 | 107,46.67 IO5.8 | 107,32.38 107,46.67 | 89.53,32.38 96.52,32.38 | 96.52,32.38 107,32.38 | 40.64,32.38 SW2.2 | 47.62,32.38 SW2.4 | 65.09,32.38 SW3.2 | 72.07,32.38 SW3.4 | 96.52,32.38 SW4.4 | 89.53,32.38 SW4.2 | 16.19,32.38 SW1.2 | 23.18,32.38 SW1.4 | 27.48,14.78 26.67,13.97 25.72,13.97 22.23,17.46 | 19.68,17.46 ISP.6 | T1.2 116.2,32.38 107,32.38 | 36.2,32.38 40.64,32.38 | 34.92,32.38 31.75,32.38 | 34.92,32.38 36.2,32.38 | 34.92,23.18 v34.92,24.77 | v34.92,31.11 34.92,32.38 | P1.1 80.64,2.54 83.19,5.08 C5.C- | 116.2,20.95 118.11,19.05 121.92,19.05 123.51,17.46 C6.C- | 11.43,32.38 9.21,32.38 C1.1 | 47.62,32.38 56.2,32.38 | 56.2,32.38 60.64,32.38 | 60.64,32.38 65.09,32.38 | 72.07,32.38 80.33,32.38 | 80.33,32.38 84.45,32.38 | 84.45,32.38 89.53,32.38 | 80.33,32.38 C3.1 | 56.2,32.38 C2.1
  Bottom 0.61: IO1.13 13.34,51.75 15.24,49.85 15.24,46.67 | 15.24,46.67 IO1.8 | 15.24,46.67 15.24,45.09 11.43,41.27 | 116.2,24.77 T3.2 | 116.2,28.57 T2.2 | IO7.1 IO8B.1 83.19,5.08
  Bottom 0.813: IO6.2 110.81,13.02 | 110.81,13.02 C9.2 | 110.81,13.02 C8.2 | 110.81,13.02 104.78,13.02 100.65,8.89 89.85,8.89 87.63,6.67 C5.C- | 116.2,32.38 116.2,28.57 116.2,24.77 116.2,20.95
  Bottom 1.016: 121.92,13.02 122.87,13.02 123.51,13.65 C6.C- | 121.92,13.02 IO6.2 | 121.92,13.02 K1.2
  pour Bottom (isolate 1.016): 0,70.48 126.68,70.48 126.68,0 0,0
MISO
  Bottom 0.406: IO9.16 32.38,11.91 32.38,11.43 30.8,9.84 24.77,9.84 ISP.1
N$1
  Bottom 0.813: T4.3 T5.2 D7.A | T4.3 56.83,5.08 | T4.3 D6.K
N$2  (via drill 0.6 pad 1.42, 0.7 pad 1.42, 0.81 pad 1.78)
  Top 0.406: v27.3,3.17 v27.3,12.38
  Bottom 0.406: IO9.19 27.73,12.7 v27.3,12.38 | 68.58,7.62 v68.58,9.53 R40.1 | 68.58,7.62 P1.3 | 68.58,7.62 P1.2 66.67,3.17 v27.3,3.17
N$3  (via drill 0.7 pad 1.68)
  Top 0.406: v8.89,46.04 v31.11,46.04
  Bottom 0.406: IO2.14 34.61,53.02 33.97,53.66 30.48,53.66 29.21,52.39 29.21,47.94 v31.11,46.04 | IO1.9 9.21,46.67 v8.89,46.04
N$4  (via drill 0.7 pad 1.68)
  Top 0.406: v34.29,46.04 v55.56,46.04
  Bottom 0.406: IO3.14 58.74,53.02 58.1,53.66 54.61,53.66 53.66,52.7 53.66,47.94 v55.56,46.04 | v34.29,46.04 34.92,46.67 IO2.9
N$5
  Bottom 0.406: DIS1.5 R10.2
N$6
  Bottom 0.406: IO1.1 17.14,55.56 R6.1
N$7
  Bottom 0.406: IO1.15 13.34,54.29 14.61,55.56 R8.1
N$8  (via drill 0.7 pad 1.68)
  Top 0.406: v82.55,46.04 v100.65,46.04
  Bottom 0.406: IO4.9 83.19,46.67 v82.55,46.04 | v100.65,46.04 98.74,47.94 98.74,52.39 100.01,53.66 101.28,53.66 101.92,53.02 IO5.14
N$9
  Bottom 0.406: IO1.2 20.95,54.29 22.23,55.56 R1.1
N$10
  Bottom 0.406: IO1.3 23.5,53.02 24.77,54.29 R2.1
N$11
  Bottom 0.406: IO1.4 23.5,51.75 24.77,50.48 R10.1
N$12
  Bottom 0.406: IO1.5 20.95,50.48 22.23,49.21 R3.1
N$13
  Bottom 0.406: IO5.4 110.81,51.75 111.44,51.12 111.44,37.15 113.67,34.92 115.57,34.92 116.52,35.88 D1.2
N$14
  Bottom 0.406: R1.2 DIS1.7
N$15
  Bottom 0.406: R2.2 DIS1.6
N$16
  Bottom 0.406: DIS1.4 R3.2
N$17
  Bottom 0.406: DIS1.2 R4.2
N$18
  Bottom 0.406: DIS1.1 R5.2
N$19
  Bottom 0.406: R6.2 DIS1.9
N$20
  Bottom 0.406: R8.2 DIS1.10
N$21
  Bottom 0.406: IO1.6 19.68,49.21 20.95,47.94 20.95,43.81 18.73,41.59 R4.1
N$22
  Bottom 0.406: IO1.7 19.05,47.94 19.68,47.31 19.68,45.4 18.41,44.13 16.19,44.13 14.61,42.55 R5.1
N$23
  Bottom 0.406: R16.1 41.59,55.56 IO2.1
N$24
  Bottom 0.406: R17.1 39.05,55.56 37.78,54.29 IO2.15
N$25
  Bottom 0.406: IO2.2 45.4,54.29 46.67,55.56 R11.1
N$26
  Bottom 0.406: IO2.3 47.94,53.02 49.21,54.29 R12.1
N$27
  Bottom 0.406: IO2.4 47.94,51.75 49.21,50.48 R18.1
N$28
  Bottom 0.406: IO2.5 45.4,50.48 46.67,49.21 R13.1
N$29
  Bottom 0.406: IO2.6 44.13,49.21 45.4,47.94 45.4,43.81 43.18,41.59 R14.1
N$30
  Bottom 0.406: IO2.7 43.5,47.94 44.13,47.31 44.13,45.4 42.86,44.13 40.64,44.13 39.05,42.55 R15.1
N$31
  Bottom 0.406: R11.2 DIS2.7
N$32
  Bottom 0.406: R12.2 DIS2.6
N$33
  Bottom 0.406: DIS2.4 R13.2
N$34
  Bottom 0.406: DIS2.2 R14.2
N$35
  Bottom 0.406: DIS2.1 R15.2
N$36
  Bottom 0.406: R16.2 DIS2.9
N$37
  Bottom 0.406: R17.2 DIS2.10
N$38
  Bottom 0.406: DIS2.5 R18.2
N$39
  Bottom 0.406: R24.1 66.04,55.56 IO3.1
N$40
  Bottom 0.406: R25.1 63.5,55.88 61.91,54.29 IO3.15
N$41
  Bottom 0.406: R19.1 71.12,55.56 69.85,54.29 IO3.2
N$42
  Bottom 0.406: R20.1 73.66,54.29 72.39,53.02 IO3.3
N$43
  Bottom 0.406: IO3.4 72.39,51.75 73.66,50.48 R26.1
N$44  (via drill 0.7 pad 1.68)
  Top 0.406: v58.74,46.04 v79.38,46.04
  Bottom 0.406: v58.74,46.04 59.37,46.67 IO3.9 | v79.38,46.04 77.47,47.94 77.47,52.7 78.42,53.66 81.92,53.66 82.55,53.02 IO4.14
N$45
  Bottom 0.406: IO3.5 69.85,50.48 71.12,49.21 R21.1
N$46
  Bottom 0.406: IO3.6 68.58,49.21 69.85,47.94 69.85,43.81 67.63,41.59 R22.1
N$47
  Bottom 0.406: IO3.7 67.94,47.94 68.58,47.31 68.58,45.4 67.31,44.13 65.09,44.13 63.5,42.55 R23.1
N$48
  Bottom 0.406: R32.1 89.85,55.56 IO4.1
N$49
  Bottom 0.406: R33.1 87.31,55.56 86.04,54.29 IO4.15
N$50
  Bottom 0.406: R27.1 94.93,55.56 93.66,54.29 IO4.2
N$51
  Bottom 0.406: IO4.3 94.93,53.02 96.2,54.29 96.2,58.74 97.47,59.69 R28.1
N$52
  Bottom 0.406: IO4.4 94.93,51.75 96.2,50.48 96.2,43.81 97.47,42.55 R34.1
N$53
  Bottom 0.406: IO4.5 93.66,50.48 94.93,49.21 R29.1
N$54
  Bottom 0.406: IO4.6 92.39,49.21 93.66,47.94 93.66,43.81 91.44,41.59 R30.1
N$55
  Bottom 0.406: IO4.7 91.76,47.94 92.39,47.31 92.39,45.4 91.12,44.13 88.9,44.13 87.31,42.55 R31.1
N$56
  Bottom 0.406: R19.2 DIS3.7
N$57
  Bottom 0.406: R20.2 DIS3.6
N$58
  Bottom 0.406: DIS3.4 R21.2
N$59
  Bottom 0.406: DIS3.2 R22.2
N$60
  Bottom 0.406: DIS3.1 R23.2
N$61
  Bottom 0.406: R24.2 DIS3.9
N$62
  Bottom 0.406: R25.2 DIS3.10
N$63
  Bottom 0.406: DIS3.5 R26.2
N$64
  Bottom 0.406: R27.2 DIS4.2
N$65
  Bottom 0.406: R28.2 DIS4.1
N$66
  Bottom 0.406: DIS4.9 R29.2
N$67
  Bottom 0.406: DIS4.7 R30.2
N$68
  Bottom 0.406: DIS4.6 R31.2
N$69
  Bottom 0.406: R32.2 DIS4.4
N$70
  Bottom 0.406: R33.2 DIS4.5
N$71
  Bottom 0.406: DIS4.10 R34.2
N$72
  Bottom 0.406: 42.86,25.72 SW2.1 39.05,25.72 36.83,27.94 33.02,27.94 28.57,23.5 28.57,22.54 29.18,21.94 IO9.31 | 42.86,25.72 SW2.3 | R58.1 42.55,25.72 42.86,25.72
N$73
  Bottom 0.406: R37.2 T1.1
N$74
  Bottom 0.406: R36.2 T2.1
N$75
  Bottom 0.406: R35.2 T3.1
N$76
  Bottom 0.406: R55.1 124.78,65.09 125.41,64.45 125.41,58.1 | 125.41,58.1 R52.1 | 125.41,37.15 125.41,44.13 | 125.41,44.13 125.41,51.12 | 125.41,51.12 125.41,58.1 | 125.41,51.12 R49.1 | 125.41,44.13 R46.1 | 125.41,37.15 R43.1 | 125.41,37.15 125.41,26.99 122.24,23.81 T3.3
N$77
  Bottom 0.406: R54.1 123.83,60.33 122.87,59.37 122.87,56.83 123.51,56.2 123.51,55.56 | 123.51,55.56 123.51,53.02 122.87,52.39 122.87,49.85 123.51,49.21 123.51,48.58 | 123.51,55.56 R51.1 | 123.51,48.58 123.51,46.04 122.87,45.4 122.87,42.86 123.51,42.23 123.51,41.59 | 123.51,41.59 123.51,39.05 122.87,38.42 122.87,35.88 123.19,35.56 R42.1 | R42.1 122.87,34.61 | 123.51,41.59 R45.1 | 123.51,48.58 R48.1 | R42.1 123.19,28.57 122.24,27.62 T2.3
N$78
  Bottom 0.406: 122.24,60.64 R50.1 | 122.24,60.64 122.24,63.5 122.56,63.82 122.56,66.67 121.6,67.63 R53.1 | 122.24,53.66 R47.1 | 122.24,53.66 122.24,60.64 | 122.24,39.69 122.24,46.67 | 122.24,46.67 122.24,53.66 | 122.24,46.67 R44.1 | 122.24,39.69 R41.1 | 122.24,39.69 122.24,35.88 121.6,35.24 T1.3
N$79
  Bottom 0.406: IO5.3 111.12,53.02 112.39,51.75 112.39,43.5 113.98,41.91 115.57,41.91 116.52,42.86 D2.2
N$80
  Bottom 0.406: D3.2 116.52,49.85 115.57,48.9 113.98,48.9 113.35,49.53 113.35,52.39 111.44,54.29 IO5.2
N$81
  Bottom 0.406: D4.2 116.52,56.83 115.25,55.56 IO5.1
N$82
  Bottom 0.406: 103.19,54.29 IO5.15 104.78,54.29 106.36,55.88 106.36,58.42 110.81,62.87 115.57,62.87 116.52,63.82 D5.2
N$83
  Bottom 0.406: SW4.3 SW4.1 87.31,27.94 R56.1 38.73,27.94 37.47,29.21 32.07,29.21 27.62,24.77 27.62,22.23 28.5,21.35 IO9.30
N$84
  Bottom 0.406: IO9.28 27.41,20.21 25.72,21.91 25.72,23.18 SW1.3 SW1.1 R59.1
N$85
  Bottom 0.406: D1.1 R41.2
N$86
  Bottom 0.406: R38.2 56.35,14.45 60.64,10.16 60.64,6.03 61.59,5.08 T4.1
N$87
  Bottom 0.406: R39.2 49.53,10.79 49.53,6.03 50.48,5.08 T5.1
N$88
  Bottom 0.406: SW3.3 SW3.1 64.77,25.4 R57.1 50.48,25.4 48.9,23.81 38.73,23.81 35.88,26.67 33.97,26.67 33.34,26.04 33.3,26.04 IO9.32
N$89
  Bottom 0.406: R42.2 119.06,34.61 118.11,35.56 D1.3
N$90
  Bottom 0.406: D1.4 R43.2
N$91
  Bottom 0.406: D2.1 R44.2
N$92
  Bottom 0.406: R45.2 119.06,41.59 118.11,42.55 D2.3
N$93
  Bottom 0.406: D2.4 R46.2
N$94
  Bottom 0.406: D3.1 R47.2
N$95
  Bottom 0.406: R48.2 119.06,48.58 118.11,49.53 D3.3
N$96
  Bottom 0.406: D3.4 R49.2
N$97
  Bottom 0.406: D4.1 R50.2
N$98
  Bottom 0.406: R51.2 119.06,55.56 118.11,56.52 D4.3
N$99
  Bottom 0.406: D4.4 R52.2
N$100
  Bottom 0.406: D5.1 R53.2
N$101
  Bottom 0.406: R54.2 119.06,62.55 118.11,63.5 D5.3
N$102
  Bottom 0.406: D5.4 R55.2
N$103
  Bottom 0.406: 45.72,5.4 45.72,5.08
  Bottom 0.813: 19.68,69.22 44.13,69.22 | 44.13,69.22 68.58,69.22 | 68.58,69.22 91.44,69.22 92.39,68.26 DIS4.3 | 19.68,69.22 DIS1.8 | 44.13,69.22 DIS2.8 | 68.58,69.22 DIS3.8 | 19.68,69.22 13.02,69.22 1.59,57.78 1.59,23.18 19.37,5.4 45.72,5.4 T5.3 D7.K
N$104
  Bottom 0.254: 6.67,15.88 6.67,15.56 6.99,15.56
R
  Bottom 0.406: IO9.13 35.95,11.75 40.64,11.75 51.12,22.23 104.14,22.23 112.39,30.48 R37.1
RESET
  Bottom 0.305: 25.08,17.46 26.99,17.46
  Bottom 0.406: 26.99,17.46 27.62,17.46 28.89,18.73 28.89,19.93 IO9.29 28.05,20.85 | 25.08,17.46 24.45,17.46 22.07,19.84 | 22.07,19.84 21.27,20.64 16.51,20.64 15.88,20 R7.1 | ISP.5 | 22.07,19.84 ISP.5
SCK
  Bottom 0.406: IO9.17 29.74,12.28 28.26,10.79 26.67,10.79 21.27,16.19 ISP.3
STROBE  (via drill 0.6 pad 1.68, 0.7 pad 1.68)
  Top 0.406: v8.89,51.75 v31.11,51.75 v33.02,51.75 v55.56,51.75 v57.47,51.75 76.83,51.75 | 76.83,51.75 77.79,51.75 | 76.83,51.75 v79.38,51.75 v81.28,51.75 v100.65,51.75
  Bottom 0.406: IO2.12 34.29,50.48 v33.02,51.75 v31.11,51.75 | IO1.12 10.16,50.48 v8.89,51.75 7.94,51.75 5.71,49.53 5.71,27.94 11.11,22.54 22.89,22.54 IO9.26 | IO3.12 58.74,50.48 v57.47,51.75 v55.56,51.75 | v79.38,51.75 v81.28,51.75 82.55,50.48 IO4.12 | IO5.12 101.92,50.48 v100.65,51.75

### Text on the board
Bottom: 2011 | PaJa | DS18B20 | Teplomer | +
Popisy: °C | 30+ | 20 | 10 | 0 | -10 | -20 | In/Out | Min | Max | Menu | Enter | - | + | Teplomer | PaJa 2011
